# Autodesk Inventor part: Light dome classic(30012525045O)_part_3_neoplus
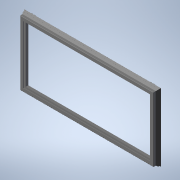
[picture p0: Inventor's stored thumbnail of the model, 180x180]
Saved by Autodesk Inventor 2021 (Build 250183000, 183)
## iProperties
Created: 2026-04
Part Number: Light dome classic(30012525045O)_part_3_neoplus
Material: Generic
Catalog Web Link: www.3dfindit.com
Description: Light dome classic_part_3_neoplus-
Vendor: KINGSPAN
Document SubType Name: Modeling
Designer: psAdmin
Manufacturer: KINGSPAN
Mass: 37251.8 g
Surface Area: 33881.5 cm^2
Volume: 37251.8 cm^3
Density: 1 g/cm^3
Appearance: PSOLRGB-255-255-255
Category: PARTsolutions
Company: KINGSPAN
Title: Light dome classic(30012525045O)_part_3_neoplus
Author: Cadenas PARTsolutions
PSOL_IDENT_0: {$CADENAS_DATA/23d-libs/kingspan_kla/light_dome_classic_neoplus/parts/part_3.prj},283 {VTYP=3D},{NB=
PSOL_IDENT_1: Light dome classic(30012525045O)_part_3_neoplus},{LINA=Light dome classic(30012525045O)_part_3_neopl
PSOL_IDENT_2: us},{NN=Light dome classic_part_3_neoplus},{DATE=20.03.2025 09:30:52},{GEOMDATE=01.07.2024 06:07:22}
PSOL_IDENT_3: ,{VERSION=},{LINEID=10},{WBVAR=LODLEVEL,L,W,DP,OP,OC},{WBNUMERIC=W}  {NB=Light dome classic(30012525
PSOL_IDENT_4: 045O)_part_3_neoplus},{LINA=Light dome classic(30012525045O)_part_3_neoplus},{KT=DUMMY},{IDNR=},{PN=
PSOL_IDENT_5: Light dome classic},{LODLEVEL=300},{L=125},{W=250},{DRIVE=1},{WX=125,250,300},{DP=4},{OP=5},{OPX='5'
PSOL_IDENT_6: ,'Pneumatic - NRWG F.6 LK'},{LX=1250},{XWX=2500},{OC=O}
NB: Light dome classic(30012525045O)_part_3_neoplus
NN: Light dome classic_part_3_neoplus
NBSYN: $PN.($LODLEVEL.$L.$W.$DP.$OP.$OC.)_part_3_neoplus
LINA: Light dome classic(30012525045O)_part_3_neoplus
CATALOG: Light + Air
PN: Light dome classic
LODLEVEL: 300
L: 125
W: 250
DP: NSHE
OP: Pneumatic - NRWG F.6 LK
OC: Open
SUPPLIER: KINGSPAN
ARTICLENO: Light dome classic(30012525045O)_part_3_neoplus
BOMINFO: Light dome classic(30012525045O)_part_3_neoplus
CREATOR: CADENAS GmbH
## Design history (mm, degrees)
sketch "Sketch_1"
  geometry: L1 (-1144, 25.446)-(-1144, 71.946); L2 (-1144, 71.946)-(-1174, 71.946); L3 (-1174, 71.946)-(-1174, 103.596); L4 (-1174, 103.596)-(-1152, 103.596); L5 (-1152, 103.596)-(-1152, 106.946); L6 (-1152, 106.946)-(-1207, 106.946); L7 (-1212, 101.946)-(-1212, 45.447); L8 (-1212, 45.447)-(-1242.031, 1.954); L9 (-1240.242, 0.252)-(-1237.688, 2.21); L10 (-1237.688, 2.21)-(-1238.863, 3.022); L11 (-1238.863, 3.022)-(-1221, 28.893); L12 (-1221, 28.893)-(-1221, 17.946); L13 (-1221, 17.946)-(-1179.25, 17.946); L14 (-1179.25, 17.946)-(-1179.25, 21.946); L15 (-1179.25, 21.946)-(-1181.25, 21.946); L16 (-1181.25, 21.946)-(-1181.25, 19.946); L17 (-1181.25, 19.946)-(-1186.75, 19.946); L18 (-1186.75, 19.946)-(-1186.75, 23.946); L19 (-1186.75, 23.946)-(-1171.2, 23.946); L20 (-1171.2, 23.946)-(-1171.2, 25.446); L21 (-1171.2, 25.446)-(-1144, 25.446); A1 r 5 centre (-1207, 101.946) between (-1207, 106.946) and (-1212, 101.946); A2 r 1.25 centre (-1241.002, 1.244) between (-1242.031, 1.954) and (-1240.242, 0.252)
  constraints: 42 end point, 4 point on circle, 2 centre point
extrude "Extrusion1" join sketch "Sketch_1" stored distance "d0" = 2500; taper "d1" = 0 deg
sketch "Sketch_2"
  geometry: L1 (582, 106.946)-(527, 106.946); L2 (527, 106.946)-(527, 103.596); L3 (527, 103.596)-(549, 103.596); L4 (549, 103.596)-(549, 71.946); L5 (549, 71.946)-(519, 71.946); L6 (519, 71.946)-(519, 25.446); L7 (519, 25.446)-(546.2, 25.446); L8 (546.2, 25.446)-(546.2, 23.946); L9 (546.2, 23.946)-(561.75, 23.946); L10 (561.75, 23.946)-(561.75, 19.946); L11 (561.75, 19.946)-(556.25, 19.946); L12 (556.25, 19.946)-(556.25, 21.946); L13 (556.25, 21.946)-(554.25, 21.946); L14 (554.25, 21.946)-(554.25, 17.946); L15 (554.25, 17.946)-(596, 17.946); L16 (596, 17.946)-(596, 28.893); L17 (596, 28.893)-(613.863, 3.022); L18 (613.863, 3.022)-(612.688, 2.21); L19 (612.688, 2.21)-(615.242, 0.252); L20 (617.031, 1.954)-(587, 45.447); L21 (587, 45.447)-(587, 101.946); A1 r 1.25 centre (616.002, 1.244) between (615.242, 0.252) and (617.031, 1.954); A2 r 5 centre (582, 101.946) between (587, 101.946) and (582, 106.946)
  constraints: 42 end point, 4 point on circle, 2 centre point
extrude "Extrusion2" join sketch "Sketch_2" stored distance "d2" = 5000; taper "d3" = 0 deg
sketch "Sketch_3"
  geometry: L1 (1242.031, 1.954)-(1212, 45.447); L2 (1212, 45.447)-(1212, 101.946); L3 (1207, 106.946)-(1152, 106.946); L4 (1152, 106.946)-(1152, 103.596); L5 (1152, 103.596)-(1174, 103.596); L6 (1174, 103.596)-(1174, 71.946); L7 (1174, 71.946)-(1144, 71.946); L8 (1144, 71.946)-(1144, 25.446); L9 (1144, 25.446)-(1171.2, 25.446); L10 (1171.2, 25.446)-(1171.2, 23.946); L11 (1171.2, 23.946)-(1186.75, 23.946); L12 (1186.75, 23.946)-(1186.75, 19.946); L13 (1186.75, 19.946)-(1181.25, 19.946); L14 (1181.25, 19.946)-(1181.25, 21.946); L15 (1181.25, 21.946)-(1179.25, 21.946); L16 (1179.25, 21.946)-(1179.25, 17.946); L17 (1179.25, 17.946)-(1221, 17.946); L18 (1221, 17.946)-(1221, 28.893); L19 (1221, 28.893)-(1238.863, 3.022); L20 (1238.863, 3.022)-(1237.688, 2.21); L21 (1237.688, 2.21)-(1240.242, 0.252); A1 r 1.25 centre (1241.002, 1.244) between (1240.242, 0.252) and (1242.031, 1.954); A2 r 5 centre (1207, 101.946) between (1212, 101.946) and (1207, 106.946)
  constraints: 42 end point, 4 point on circle, 2 centre point
extrude "Extrusion3" join sketch "Sketch_3" stored distance "d4" = 2500; taper "d5" = 0 deg
sketch "Sketch_4"
  geometry: L1 (-527, 106.946)-(-582, 106.946); L2 (-587, 101.946)-(-587, 45.447); L3 (-587, 45.447)-(-617.031, 1.954); L4 (-615.242, 0.252)-(-612.688, 2.21); L5 (-612.688, 2.21)-(-613.863, 3.022); L6 (-613.863, 3.022)-(-596, 28.893); L7 (-596, 28.893)-(-596, 17.946); L8 (-596, 17.946)-(-554.25, 17.946); L9 (-554.25, 17.946)-(-554.25, 21.946); L10 (-554.25, 21.946)-(-556.25, 21.946); L11 (-556.25, 21.946)-(-556.25, 19.946); L12 (-556.25, 19.946)-(-561.75, 19.946); L13 (-561.75, 19.946)-(-561.75, 23.946); L14 (-561.75, 23.946)-(-546.2, 23.946); L15 (-546.2, 23.946)-(-546.2, 25.446); L16 (-546.2, 25.446)-(-519, 25.446); L17 (-519, 25.446)-(-519, 71.946); L18 (-519, 71.946)-(-549, 71.946); L19 (-549, 71.946)-(-549, 103.596); L20 (-549, 103.596)-(-527, 103.596); L21 (-527, 103.596)-(-527, 106.946); A1 r 5 centre (-582, 101.946) between (-582, 106.946) and (-587, 101.946); A2 r 1.25 centre (-616.002, 1.244) between (-617.031, 1.954) and (-615.242, 0.252)
  constraints: 42 end point, 4 point on circle, 2 centre point
extrude "Extrusion4" join sketch "Sketch_4" stored distance "d6" = 5000; taper "d7" = 0 deg
sketch "Sketch_5"
  geometry: L1 (-1152, 156.946)-(-2500, 156.946); L2 (-2500, 156.946)-(-2500, -32.054); L3 (-2500, -32.054)-(-1241.002, -32.054); L4 (-1241.002, -32.054)-(-1241.002, -0.006); L5 (-1242.031, 1.954)-(-1212, 45.447); L6 (-1212, 45.447)-(-1212, 101.946); L7 (-1207, 106.946)-(-1152, 106.946); L8 (-1152, 106.946)-(-1152, 156.946); A1 r 1.25 centre (-1241.002, 1.244) between (-1242.031, 1.954) and (-1241.002, -0.006); A2 r 5 centre (-1207, 101.946) between (-1207, 106.946) and (-1212, 101.946)
  constraints: 16 end point, 4 point on circle, 2 centre point
extrude "Extrusion5" cut sketch "Sketch_5" stored distance "d8" = 2500; taper "d9" = 0 deg
sketch "Sketch_6"
  geometry: L1 (2500, 156.946)-(1152, 156.946); L2 (1152, 156.946)-(1152, 106.946); L3 (1152, 106.946)-(1207, 106.946); L4 (1212, 101.946)-(1212, 45.447); L5 (1212, 45.447)-(1242.031, 1.954); L6 (1241.002, -0.006)-(1241.002, -32.054); L7 (1241.002, -32.054)-(2500, -32.054); L8 (2500, -32.054)-(2500, 156.946); A1 r 5 centre (1207, 101.946) between (1212, 101.946) and (1207, 106.946); A2 r 1.25 centre (1241.002, 1.244) between (1241.002, -0.006) and (1242.031, 1.954)
  constraints: 16 end point, 4 point on circle, 2 centre point
extrude "Extrusion6" cut sketch "Sketch_6" stored distance "d10" = 2500; taper "d11" = 0 deg
sketch "Sketch_7"
  geometry: L1 (1250, 156.946)-(527, 156.946); L2 (527, 156.946)-(527, 106.946); L3 (527, 106.946)-(582, 106.946); L4 (587, 101.946)-(587, 45.447); L5 (587, 45.447)-(617.031, 1.954); L6 (616.002, -0.006)-(616.002, -32.054); L7 (616.002, -32.054)-(1250, -32.054); L8 (1250, -32.054)-(1250, 156.946); A1 r 5 centre (582, 101.946) between (587, 101.946) and (582, 106.946); A2 r 1.25 centre (616.002, 1.244) between (616.002, -0.006) and (617.031, 1.954)
  constraints: 16 end point, 4 point on circle, 2 centre point
extrude "Extrusion7" cut sketch "Sketch_7" stored distance "d12" = 5000; taper "d13" = 0 deg
sketch "Sketch_8"
  geometry: L1 (-1250, 156.946)-(-1250, -32.054); L2 (-1250, -32.054)-(-616.002, -32.054); L3 (-616.002, -32.054)-(-616.002, -0.006); L4 (-617.031, 1.954)-(-587, 45.447); L5 (-587, 45.447)-(-587, 101.946); L6 (-582, 106.946)-(-527, 106.946); L7 (-527, 106.946)-(-527, 156.946); L8 (-527, 156.946)-(-1250, 156.946); A1 r 1.25 centre (-616.002, 1.244) between (-617.031, 1.954) and (-616.002, -0.006); A2 r 5 centre (-582, 101.946) between (-582, 106.946) and (-587, 101.946)
  constraints: 16 end point, 4 point on circle, 2 centre point
extrude "Extrusion8" cut sketch "Sketch_8" stored distance "d14" = 5000; taper "d15" = 0 deg
sketch "Sketch_9"
  geometry: L1 (-1207, 34.19)-(-1207, 71.429); L2 (-1207, 71.429)-(-1233.061, 32.792); L3 (-1231.277, 31.71)-(-1228.348, 34.19); L4 (-1228.348, 34.19)-(-1207, 34.19); A1 r 1.1 centre (-1231.988, 32.55) between (-1233.061, 32.792) and (-1231.277, 31.71)
  constraints: 8 end point, 2 point on circle, 1 centre point
extrude "Extrusion9" join sketch "Sketch_9" stored distance "d16" = 2500; taper "d17" = 0 deg
sketch "Sketch_10"
  geometry: L1 (582, 71.429)-(582, 34.19); L2 (582, 34.19)-(603.348, 34.19); L3 (603.348, 34.19)-(606.277, 31.71); L4 (608.061, 32.792)-(582, 71.429); A1 r 1.1 centre (606.988, 32.55) between (606.277, 31.71) and (608.061, 32.792)
  constraints: 8 end point, 2 point on circle, 1 centre point
extrude "Extrusion10" join sketch "Sketch_10" stored distance "d18" = 5000; taper "d19" = 0 deg
sketch "Sketch_11"
  geometry: L1 (1233.061, 32.792)-(1207, 71.429); L2 (1207, 71.429)-(1207, 34.19); L3 (1207, 34.19)-(1228.348, 34.19); L4 (1228.348, 34.19)-(1231.277, 31.71); A1 r 1.1 centre (1231.988, 32.55) between (1231.277, 31.71) and (1233.061, 32.792)
  constraints: 8 end point, 2 point on circle, 1 centre point
extrude "Extrusion11" join sketch "Sketch_11" stored distance "d20" = 2500; taper "d21" = 0 deg
sketch "Sketch_12"
  geometry: L1 (-582, 71.429)-(-608.061, 32.792); L2 (-606.277, 31.71)-(-603.348, 34.19); L3 (-603.348, 34.19)-(-582, 34.19); L4 (-582, 34.19)-(-582, 71.429); A1 r 1.1 centre (-606.988, 32.55) between (-608.061, 32.792) and (-606.277, 31.71)
  constraints: 8 end point, 2 point on circle, 1 centre point
extrude "Extrusion12" join sketch "Sketch_12" stored distance "d22" = 5000; taper "d23" = 0 deg
sketch "Sketch_13"
  geometry: L1 (-1212, 74.016)-(-3731.988, 74.016); L2 (-3731.988, 74.016)-(-3731.988, 27.946); L3 (-3731.988, 27.946)-(-1231.988, 27.946); L4 (-1231.988, 27.946)-(-1231.988, 31.45); L5 (-1233.061, 32.792)-(-1212, 64.016); L6 (-1212, 64.016)-(-1212, 74.016); A1 r 1.1 centre (-1231.988, 32.55) between (-1233.061, 32.792) and (-1231.988, 31.45)
  constraints: 12 end point, 2 point on circle, 1 centre point
extrude "Extrusion13" cut sketch "Sketch_13" stored distance "d24" = 2500; taper "d25" = 0 deg
sketch "Sketch_14"
  geometry: L1 (3731.988, 27.946)-(3731.988, 74.016); L2 (3731.988, 74.016)-(1212, 74.016); L3 (1212, 74.016)-(1212, 64.016); L4 (1212, 64.016)-(1233.061, 32.792); L5 (1231.988, 31.45)-(1231.988, 27.946); L6 (1231.988, 27.946)-(3731.988, 27.946); A1 r 1.1 centre (1231.988, 32.55) between (1231.988, 31.45) and (1233.061, 32.792)
  constraints: 12 end point, 2 point on circle, 1 centre point
extrude "Extrusion14" cut sketch "Sketch_14" stored distance "d26" = 2500; taper "d27" = 0 deg
sketch "Sketch_15"
  geometry: L1 (1856.988, 74.016)-(587, 74.016); L2 (587, 74.016)-(587, 64.016); L3 (587, 64.016)-(608.061, 32.792); L4 (606.988, 31.45)-(606.988, 27.946); L5 (606.988, 27.946)-(1856.988, 27.946); L6 (1856.988, 27.946)-(1856.988, 74.016); A1 r 1.1 centre (606.988, 32.55) between (606.988, 31.45) and (608.061, 32.792)
  constraints: 12 end point, 2 point on circle, 1 centre point
extrude "Extrusion15" cut sketch "Sketch_15" stored distance "d28" = 5000; taper "d29" = 0 deg
sketch "Sketch_16"
  geometry: L1 (-1856.988, 74.016)-(-1856.988, 27.946); L2 (-1856.988, 27.946)-(-606.988, 27.946); L3 (-606.988, 27.946)-(-606.988, 31.45); L4 (-608.061, 32.792)-(-587, 64.016); L5 (-587, 64.016)-(-587, 74.016); L6 (-587, 74.016)-(-1856.988, 74.016); A1 r 1.1 centre (-606.988, 32.55) between (-608.061, 32.792) and (-606.988, 31.45)
  constraints: 12 end point, 2 point on circle, 1 centre point
extrude "Extrusion16" cut sketch "Sketch_16" stored distance "d30" = 5000; taper "d31" = 0 deg
sketch "Sketch_17"
  geometry: L1 (-17.946, 574.665)-(-16.1, 570.05); L2 (-16.1, 570.05)-(-14.243, 570.793); L3 (-14.243, 570.793)-(-15.946, 575.05); L4 (-15.946, 575.05)-(-15.946, 595.837); L5 (-15.946, 595.837)-(7.12, 614.184); L6 (6.644, 612.499)-(4.764, 611.817); L7 (5.875, 615.749)-(-17.946, 596.802); L8 (-17.946, 596.802)-(-17.946, 574.665); A1 r 1.5 centre (8.054, 613.01) between (6.644, 612.499) and (7.12, 614.184); A2 r 3.5 centre (8.054, 613.01) between (4.764, 611.817) and (5.875, 615.749)
  constraints: 16 end point, 4 point on circle, 2 centre point
extrude "Extrusion17" join sketch "Sketch_17" distance "d32" = 70; taper "d33" = 0 deg
sketch "Sketch_18"
  geometry: L1 (-17.946, 574.665)-(-16.1, 570.05); L2 (-16.1, 570.05)-(-14.243, 570.793); L3 (-14.243, 570.793)-(-15.946, 575.05); L4 (-15.946, 575.05)-(-15.946, 595.837); L5 (-15.946, 595.837)-(7.12, 614.184); L6 (6.644, 612.499)-(4.764, 611.817); L7 (5.875, 615.749)-(-17.946, 596.802); L8 (-17.946, 596.802)-(-17.946, 574.665); A1 r 1.5 centre (8.054, 613.01) between (6.644, 612.499) and (7.12, 614.184); A2 r 3.5 centre (8.054, 613.01) between (4.764, 611.817) and (5.875, 615.749)
  constraints: 16 end point, 4 point on circle, 2 centre point
extrude "Extrusion18" join sketch "Sketch_18" distance "d34" = 70; taper "d35" = 0 deg
sketch "Sketch_19"
  geometry: L1 (-15.946, 636.757)-(16.193, 598.455); L2 (16.193, 598.455)-(31.514, 611.311); L3 (31.514, 611.311)-(-0.625, 649.613); L4 (-0.625, 649.613)-(-15.946, 636.757)
  constraints: 8 end point
extrude "Extrusion19" cut sketch "Sketch_19" stored distance "d36" = 38; taper "d37" = 0 deg
sketch "Sketch_20"
  geometry: L1 (-15.946, 636.757)-(16.193, 598.455); L2 (16.193, 598.455)-(31.514, 611.311); L3 (31.514, 611.311)-(-0.625, 649.613); L4 (-0.625, 649.613)-(-15.946, 636.757)
  constraints: 8 end point
extrude "Extrusion20" cut sketch "Sketch_20" stored distance "d38" = 38; taper "d39" = 0 deg
sketch "Sketch_21"
  geometry: L1 (-634.411, -2.354)-(-612.41, -2.354); L2 (-612.41, -2.354)-(-612.41, 8.646); L3 (-612.41, 8.646)-(-610.722, 11.091); L4 (-610.722, 11.091)-(-616.711, 19.644); A1 r 20 centre (-616.411, -0.354) between (-616.711, 19.644) and (-636.411, -0.354); A2 r 2 centre (-634.411, -0.354) between (-636.411, -0.354) and (-634.411, -2.354)
  constraints: 8 end point, 4 point on circle, 2 centre point
extrude "Extrusion21" join sketch "Sketch_21" stored distance "d40" = 41; taper "d41" = 0 deg
node "IP_3_XY"
node "IP_3_YZ"
node "IP_3_ZX"
node "IP_3_X"
node "IP_3_Y"
node "IP_3_Z"
node "IP_3_Center"
node "IP_for_part_11_1_XY"
node "IP_for_part_11_1_YZ"
node "IP_for_part_11_1_ZX"
node "IP_for_part_11_1_X"
node "IP_for_part_11_1_Y"
node "IP_for_part_11_1_Z"
node "IP_for_part_11_1_Center"
node "IP_for_part_4_XY"
node "IP_for_part_4_YZ"
node "IP_for_part_4_ZX"
node "IP_for_part_4_X"
node "IP_for_part_4_Y"
node "IP_for_part_4_Z"
node "IP_for_part_4_Center"
node "IP_for_part_5_XY"
node "IP_for_part_5_YZ"
node "IP_for_part_5_ZX"
node "IP_for_part_5_X"
node "IP_for_part_5_Y"
node "IP_for_part_5_Z"
node "IP_for_part_5_Center"
node "IP_for_part_6_XY"
node "IP_for_part_6_YZ"
node "IP_for_part_6_ZX"
node "IP_for_part_6_X"
node "IP_for_part_6_Y"
node "IP_for_part_6_Z"
node "IP_for_part_6_Center"
body "Solid1"
other parameters: "d42" = 0, "d43" = 0, "d44" = 0
